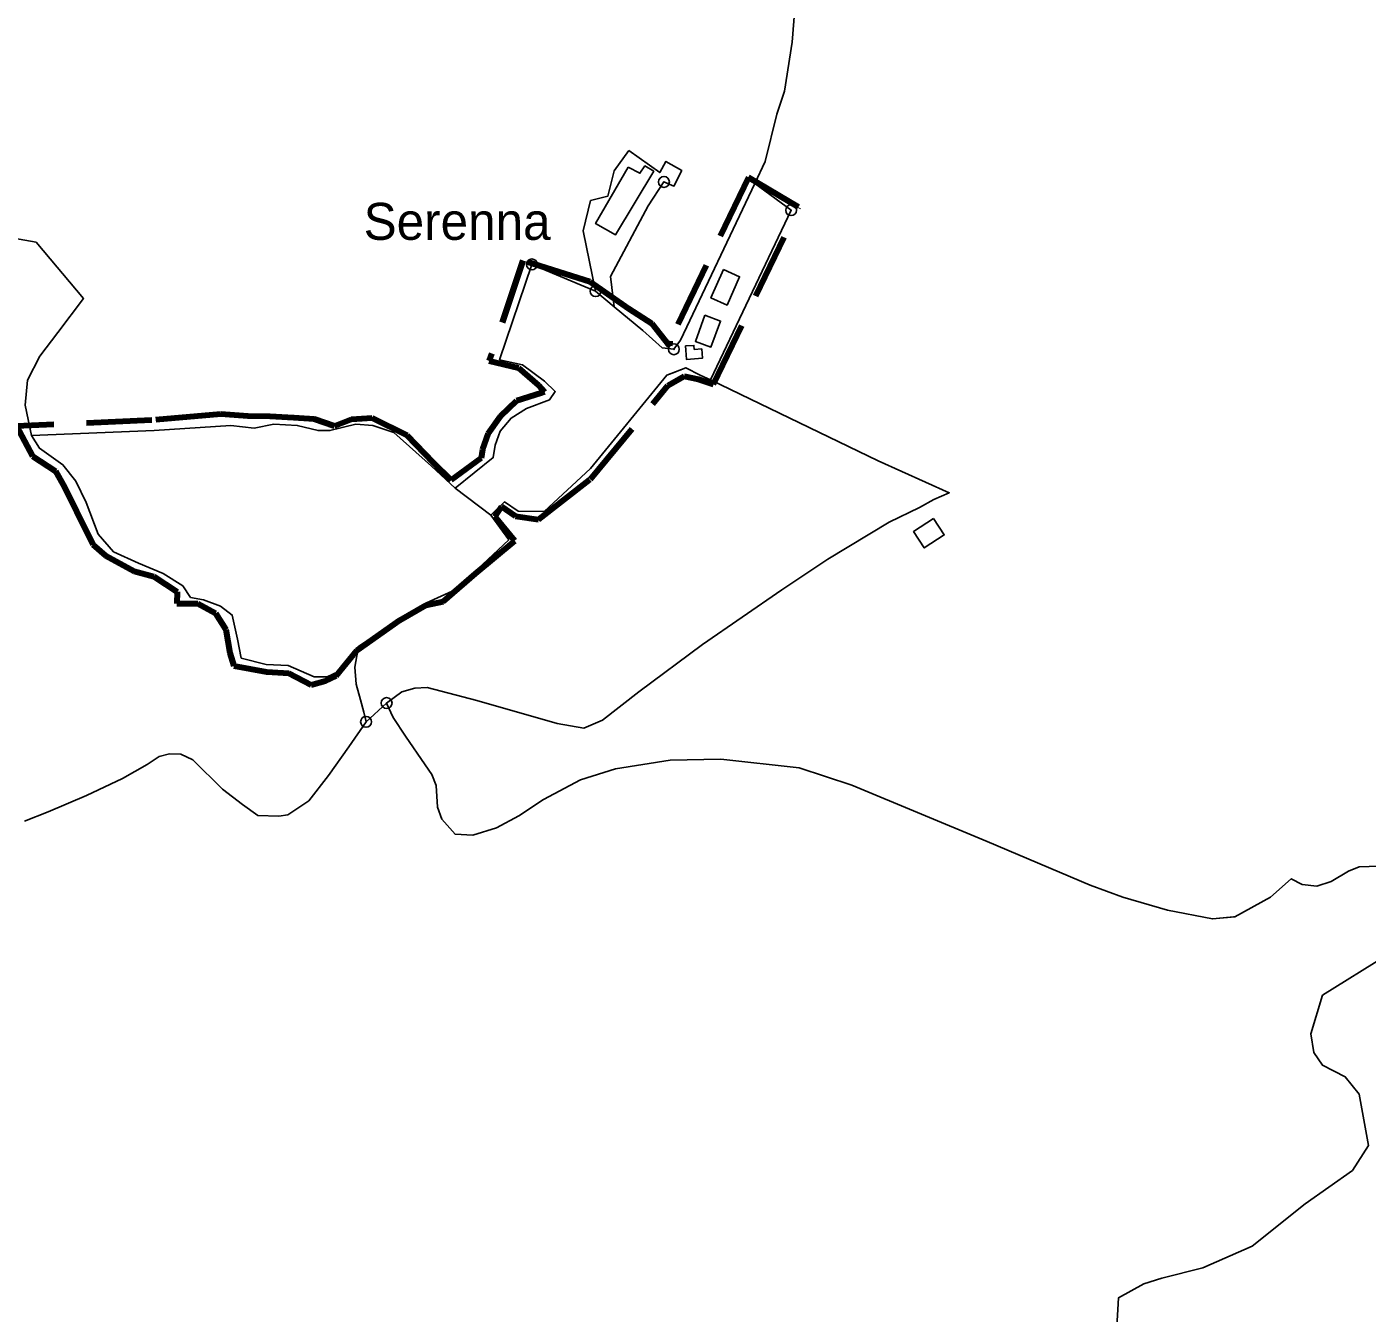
# Model space of a CAD drawing. Extents: x 645880 to 658994, y 884400 to 894744.
# Drawn here: x 653285 to 653901, y 890509 to 891100 of the extents above; entities that cross this region are included whole.
import ezdxf
from ezdxf.enums import TextEntityAlignment as Align

# ---------------------------------------------------------------- set-up
doc = ezdxf.new("R2010")
doc.units = 0
doc.header["$LTSCALE"] = 10
doc.header["$PDMODE"] = 32
doc.header["$PDSIZE"] = 5
doc.linetypes.add('MEDIUM_DASHED', pattern=[4.5, 3, -1.5])
for name, color, linetype, lineweight in [('15', 7, 'MEDIUM_DASHED', 100), ('16', 7, 'Continuous', 25), ('17', 7, 'Continuous', 25), ('18', 7, 'Continuous', 25), ('3', 7, 'Continuous', 25), ('6', 7, 'Continuous', 25), ('7', 7, 'Continuous', 25), ('8', 7, 'Continuous', 25)]:
    doc.layers.add(name, color=color, linetype=linetype, lineweight=lineweight)
doc.layers.add('60', color=7, linetype='Continuous')

msp = doc.modelspace()

# ---------------------------------------------------------------- linework, layer by layer
at = {"layer": '15'}
for points in [[(653579.74, 890934.93), (653587.25, 890939.26), (653593.79, 890937.88), (653600.67, 890935.57), (653639.74, 891016.9), (653616.77, 891030.65), (653580.62, 890955.46), (653580.39, 890953.16), (653572.51, 890963.35), (653561.73, 890970.28), (653544, 890982.62), (653513.07, 890992.41), (653497.63, 890946.24), (653510.98, 890943.02), (653520.2, 890935.18), (653523.03, 890932.03), (653521.28, 890931.5), (653510.11, 890927.88), (653502.7, 890920.9), (653497.1, 890912.86), (653494.47, 890905.62), (653493.95, 890901.54), (653480.13, 890891.4), (653471.79, 890899.62), (653459.82, 890912.06), (653443.74, 890919.98), (653434.21, 890919.4), (653426.51, 890916.32), (653417.04, 890919.52), (653407.7, 890920.07), (653396.92, 890920.65), (653386.64, 890920.9), (653374.2, 890921.82), (653342.43, 890919.05), (653280.25, 890916.29), (653287.62, 890902.46), (653298.21, 890895.55), (653302.36, 890888.18), (653307.88, 890877.12), (653315.29, 890861.83)], [(653315.29, 890861.83), (653321.24, 890856.84), (653334.3, 890849.7), (653343.35, 890847.16), (653354.06, 890840.06), (653353.93, 890834.79), (653363.65, 890834.69), (653371.73, 890830.25), (653376.51, 890822.74), (653378.35, 890812.14), (653380.19, 890806.15), (653395.2, 890803.35), (653405.38, 890802.77), (653415.66, 890797.39), (653422.38, 890799.18), (653427.17, 890801.51), (653436.75, 890813.12), (653456.51, 890827.07), (653468.49, 890834.04), (653476.45, 890835.64), (653491.24, 890848.56), (653509.34, 890863.62), (653500.1, 890874.72), (653503.3, 890879.29), (653509.59, 890874.93), (653520.2, 890873.43), (653544.09, 890891.98), (653579.74, 890934.93)]]:
    msp.add_lwpolyline(points, dxfattribs=at)
at = {"layer": '16'}
msp.add_line((653636.37, 891015.55), (653599.27, 890937.51), dxfattribs=at)
for points in [[(653619.68, 891027.76), (653624.41, 891037.97), (653629.84, 891059.69), (653633.37, 891070.27), (653636.89, 891092.8), (653640.15, 891135.42), (653642.05, 891141.93), (653643.67, 891148.99), (653643.95, 891159.03), (653643.67, 891179.39), (653645.03, 891184.55), (653649.1, 891190.52), (653654.8, 891196.49), (653668.91, 891209.25), (653681.93, 891222.28), (653689.52, 891233.95), (653699.56, 891246.44), (653704.17, 891250.78), (653709.06, 891253.23), (653718.01, 891255.13), (653726.72, 891256.83)], [(653726.72, 891256.83), (653718.01, 891255.13), (653709.06, 891253.23), (653704.17, 891250.78), (653699.56, 891246.44), (653689.52, 891233.95), (653681.93, 891222.28), (653668.91, 891209.25), (653654.8, 891196.49), (653649.1, 891190.52), (653645.03, 891184.55), (653643.67, 891179.39), (653643.95, 891159.03), (653643.67, 891148.99), (653642.05, 891141.93), (653640.15, 891135.42), (653636.89, 891092.8), (653633.37, 891070.27), (653629.84, 891059.69), (653624.41, 891037.97), (653619.68, 891027.76), (653636.37, 891015.55)], [(653517.18, 890990.64), (653546.51, 890978.34), (653540.77, 891006.13), (653544.18, 891019.95), (653552.09, 891021.97), (653555.04, 891033.62), (653561.72, 891042.94)], [(653561.72, 891042.94), (653575.99, 891032.84), (653578.79, 891037.97), (653586.08, 891033.78), (653582.49, 891026.67), (653577.89, 891028.57)], [(653577.89, 891028.57), (653570.69, 891017.57), (653553.29, 890985.07), (653554.99, 890971.17), (653568.15, 890960.31), (653577.14, 890952.31), (653582.47, 890951.64)], [(653582.47, 890951.64), (653585.5, 890955.86), (653619.68, 891027.76)], [(653270.89, 891004.08), (653289.25, 891000.94), (653311.03, 890974.91), (653299.18, 890959.41), (653290.94, 890948.41), (653285.27, 890937.41), (653284.24, 890925.92), (653287.2, 890911.94), (653343.48, 890914.27), (653378.81, 890916.59), (653389.59, 890915.43), (653398.57, 890917.17), (653409.35, 890916.59), (653418.93, 890914.27), (653424.32, 890914.27), (653436.29, 890917.17), (653444.08, 890916.59), (653453.66, 890913.39), (653471.08, 890897.92), (653481.93, 890887.72), (653499.45, 890901.84), (653500.33, 890907.59), (653502.54, 890914), (653507.62, 890919.98), (653514.69, 890924.4), (653525.3, 890928.38), (653527.95, 890932.14), (653523.01, 890936.93), (653512.82, 890944.49), (653502.31, 890946.8), (653517.18, 890990.64)], [(653599.27, 890937.51), (653676.42, 890900.31), (653709.07, 890885.64), (653702.04, 890882.5), (653695.46, 890878.92), (653681.51, 890872.22), (653653.19, 890855.2), (653632.13, 890841.1), (653595.63, 890815.96), (653566.37, 890794.23), (653549.69, 890781.08), (653541.04, 890777.46), (653528.8, 890779.62), (653491.84, 890790.2), (653469.03, 890796.12), (653463.31, 890795.83), (653457.39, 890794.18), (653450.4, 890789)], [(653450.4, 890789), (653453.39, 890782.33), (653459.06, 890773.83), (653468.07, 890760.58), (653471.17, 890756.08), (653473.23, 890751.09), (653473.74, 890741.09), (653475.8, 890735.59), (653481.88, 890728.71), (653490.12, 890728.21), (653500.94, 890731.71), (653511.25, 890737.21), (653522.58, 890744.71), (653539.59, 890753.71), (653555.56, 890758.71), (653580.81, 890762.71), (653604, 890763.21), (653640.07, 890759.21), (653664.28, 890751.21), (653726.46, 890725.28), (653773.87, 890705.29), (653788.81, 890699.79), (653809.42, 890693.79), (653830.03, 890689.79), (653839.8, 890690.74), (653840.34, 890690.79), (653856.83, 890699.79), (653866.29, 890708.25), (653871.3, 890705.63), (653878, 890704.87), (653884.67, 890707.03), (653892.59, 890711.76), (653897.6, 890713.71), (653911.09, 890714.24)], [(653910.22, 890673.13), (653880.64, 890654.7), (653875.38, 890636.93), (653876.69, 890628.38), (653880.64, 890622.46), (653891.15, 890617.19), (653897.59, 890609.27), (653901.81, 890585.53), (653894.43, 890574.19), (653872.76, 890558.85), (653848.3, 890539.37), (653825.63, 890529.35), (653806.82, 890524.57), (653798.58, 890522.07), (653786.89, 890515.64), (653786.1, 890502.18)]]:
    msp.add_lwpolyline(points, dxfattribs=at)
for p in [(653577.89, 891028.57), (653636.37, 891015.55), (653517.18, 890990.64), (653582.47, 890951.64), (653450.4, 890789)]:
    msp.add_point(p, dxfattribs=at)
at = {"layer": '17'}
msp.add_lwpolyline([(653437.52, 890814.95), (653456.79, 890827.96), (653468.72, 890835.04), (653480.6, 890840.49), (653491.98, 890850.36), (653506.52, 890864.02), (653498.29, 890875.39), (653504.58, 890881.49), (653510.87, 890877.13), (653522.87, 890877.06), (653544.1, 890896.89), (653579.23, 890939.66), (653581.65, 890940.62), (653587.96, 890943.13), (653594.53, 890939.68), (653599.27, 890937.51), (653676.42, 890900.31), (653709.07, 890885.64), (653702.04, 890882.5), (653695.46, 890878.92), (653681.51, 890872.22), (653653.19, 890855.2), (653632.13, 890841.1), (653595.63, 890815.96), (653566.37, 890794.23), (653549.69, 890781.08), (653541.04, 890777.46), (653528.8, 890779.62), (653491.84, 890790.2), (653469.03, 890796.12), (653463.31, 890795.83), (653457.39, 890794.18), (653450.4, 890789), (653440.94, 890780.36), (653439.88, 890784.81), (653438.42, 890790.46), (653436.36, 890797.71), (653435.85, 890805.46)], close=True, dxfattribs=at)
at = {"layer": '18'}
for points in [[(653440.94, 890780.36), (653439.88, 890784.81), (653438.42, 890790.46), (653436.36, 890797.71), (653435.85, 890805.46), (653437.52, 890814.95), (653427.91, 890803.31), (653423.15, 890801.01), (653417.16, 890801.01), (653405.16, 890806.21), (653394.98, 890806.79), (653383.6, 890809.7), (653381.81, 890818.41), (653379.41, 890829.45), (653374.02, 890833.51), (653366.24, 890836.42), (653360.25, 890837.58), (653356.66, 890842.81), (653347.68, 890848.62), (653336.3, 890853.27), (653324.92, 890858.5), (653317.74, 890866.63), (653312.35, 890881.15), (653307.56, 890891.03), (653301.57, 890898.58), (653290.79, 890906.13), (653287.2, 890911.94), (653284.24, 890925.92), (653285.27, 890937.41), (653290.94, 890948.41), (653299.18, 890959.41), (653311.03, 890974.91), (653289.25, 891000.94), (653270.89, 891004.08)], [(653788.81, 890699.79), (653773.87, 890705.29), (653726.46, 890725.28), (653664.28, 890751.21), (653640.07, 890759.21), (653604, 890763.21), (653580.81, 890762.71), (653555.56, 890758.71), (653539.59, 890753.71), (653522.58, 890744.71), (653511.25, 890737.21), (653500.94, 890731.71), (653490.12, 890728.21), (653481.88, 890728.71), (653475.8, 890735.59), (653473.74, 890741.09), (653473.23, 890751.09), (653471.17, 890756.08), (653468.07, 890760.58), (653459.06, 890773.83), (653453.39, 890782.33), (653450.4, 890789), (653440.94, 890780.36)], [(653440.94, 890780.36), (653433.09, 890768.92), (653423.69, 890755.66), (653414.72, 890744.11), (653404.96, 890737.67), (653400.9, 890737.02), (653391.21, 890737.27), (653384.16, 890742.4), (653374.97, 890749.47), (653361.3, 890762.94), (653355.74, 890765.5), (653350.61, 890765.72), (653345.91, 890764.43), (653340.36, 890760.8), (653329.03, 890754.38), (653312.37, 890746.48), (653294.84, 890739), (653283.94, 890734.72)], [(653283.94, 890734.72), (653294.84, 890739), (653312.37, 890746.48), (653329.03, 890754.38), (653340.36, 890760.8), (653345.91, 890764.43), (653350.61, 890765.72), (653355.74, 890765.5), (653361.3, 890762.94), (653374.97, 890749.47), (653384.16, 890742.4), (653391.21, 890737.27), (653400.9, 890737.02), (653404.96, 890737.67), (653414.72, 890744.11), (653423.69, 890755.66), (653433.09, 890768.92), (653440.94, 890780.36)], [(653911.09, 890714.24), (653897.6, 890713.71), (653892.59, 890711.76), (653884.67, 890707.03), (653878, 890704.87), (653871.3, 890705.63), (653866.29, 890708.25), (653856.83, 890699.79), (653840.34, 890690.79), (653830.03, 890689.79), (653809.42, 890693.79), (653788.81, 890699.79)], [(653786.1, 890502.18), (653786.89, 890515.64), (653798.58, 890522.07), (653806.82, 890524.57), (653825.63, 890529.35), (653848.3, 890539.37), (653872.76, 890558.85), (653894.43, 890574.19), (653901.81, 890585.53), (653897.59, 890609.27), (653891.15, 890617.19), (653880.64, 890622.46), (653876.69, 890628.38), (653875.38, 890636.93), (653880.64, 890654.7), (653910.22, 890673.13)]]:
    msp.add_lwpolyline(points, dxfattribs=at)
msp.add_point((653440.94, 890780.36), dxfattribs=at)
at = {"layer": '3'}
for points in [[(653546.51, 890978.34), (653540.77, 891006.13), (653544.18, 891019.95), (653552.09, 891021.97), (653555.04, 891033.62), (653561.72, 891042.94)], [(653561.72, 891042.94), (653575.99, 891032.84), (653578.79, 891037.97), (653586.08, 891033.78), (653582.49, 891026.67), (653577.89, 891028.57)], [(653577.89, 891028.57), (653570.69, 891017.57), (653553.29, 890985.07), (653554.99, 890971.17), (653546.51, 890978.34)]]:
    msp.add_lwpolyline(points, dxfattribs=at)
msp.add_lwpolyline([(653561.41, 891035.33), (653546.51, 891009.39), (653555.67, 891004.27), (653573.2, 891033.46), (653569.17, 891035.95), (653566.84, 891032.53)], close=True, dxfattribs=at)
for p in [(653577.89, 891028.57), (653546.51, 890978.34)]:
    msp.add_point(p, dxfattribs=at)
at = {"layer": '6'}
msp.add_lwpolyline([(653701.85, 890873.87), (653692.64, 890867.85), (653697.58, 890860.29), (653706.79, 890866.31)], close=True, dxfattribs=at)
at = {"layer": '7'}
for points in [[(653605.24, 890988.26), (653599.48, 890975.22), (653606.93, 890971.93), (653612.69, 890984.97)], [(653596.74, 890967.23), (653592.35, 890955.25), (653599.53, 890952.62), (653603.92, 890964.6)], [(653587.96, 890951.26), (653588.23, 890947), (653595.58, 890947.47), (653595.31, 890951.77), (653591.82, 890951.55), (653591.7, 890953.42), (653587.84, 890953.18)]]:
    msp.add_lwpolyline(points, close=True, dxfattribs=at)
at = {"layer": '8'}
msp.add_line((653287.2, 890911.94), (653343.48, 890914.27), dxfattribs=at)
msp.add_lwpolyline([(653577.14, 890952.31), (653568.15, 890960.31), (653554.99, 890971.17), (653546.51, 890978.34), (653517.18, 890990.64), (653502.31, 890946.8), (653512.82, 890944.49), (653523.01, 890936.93), (653527.95, 890932.14), (653525.3, 890928.38), (653514.69, 890924.4), (653507.62, 890919.98), (653502.54, 890914), (653500.33, 890907.59), (653499.45, 890901.84), (653481.93, 890887.72), (653498.29, 890875.39), (653504.58, 890881.49), (653510.87, 890877.13), (653522.87, 890877.06), (653544.1, 890896.89), (653579.23, 890939.66), (653587.96, 890943.13), (653594.53, 890939.68), (653599.27, 890937.51), (653636.37, 891015.55), (653619.68, 891027.76), (653585.5, 890955.86), (653582.47, 890951.64)], close=True, dxfattribs=at)
msp.add_lwpolyline([(653343.48, 890914.27), (653378.81, 890916.59), (653389.59, 890915.43), (653398.57, 890917.17), (653409.35, 890916.59), (653418.93, 890914.27), (653424.32, 890914.27), (653436.29, 890917.17), (653444.08, 890916.59), (653453.66, 890913.39), (653471.08, 890897.92), (653481.93, 890887.72), (653498.29, 890875.39), (653506.52, 890864.02), (653491.98, 890850.36), (653480.6, 890840.49), (653468.72, 890835.04), (653456.79, 890827.96), (653437.52, 890814.95), (653427.91, 890803.31), (653423.15, 890801.01), (653417.16, 890801.01), (653405.16, 890806.21), (653394.98, 890806.79), (653383.6, 890809.7), (653381.81, 890818.41), (653379.41, 890829.45), (653374.02, 890833.51), (653366.24, 890836.42), (653360.25, 890837.58), (653356.66, 890842.81), (653347.68, 890848.62), (653336.3, 890853.27), (653324.92, 890858.5), (653317.74, 890866.63), (653312.35, 890881.15), (653307.56, 890891.03), (653301.57, 890898.58), (653290.79, 890906.13), (653287.2, 890911.94)], dxfattribs=at)

# ---------------------------------------------------------------- texts
at = {"layer": '60'}
msp.add_text('Serenna', height=17, dxfattribs=at).set_placement((653482.82, 891001.93), align=Align.CENTER)

doc.saveas('drawing.dxf')
